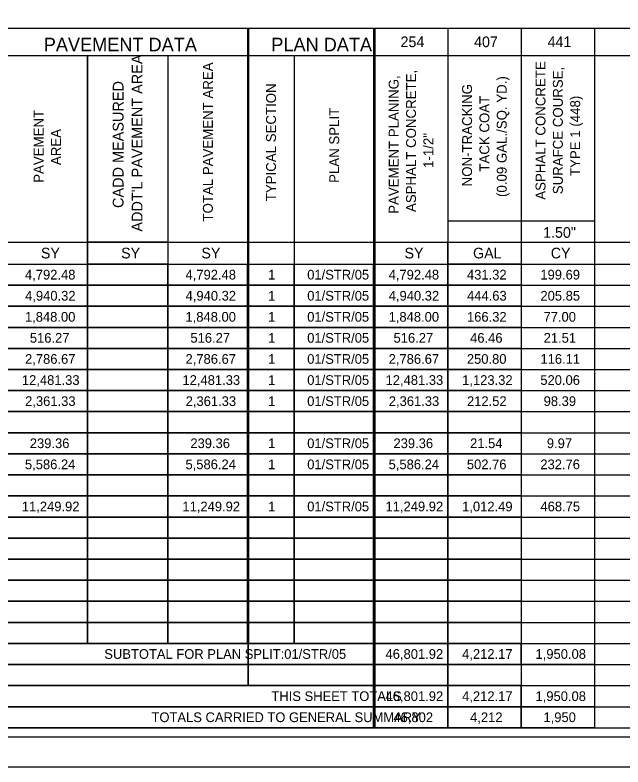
# Model space of a CAD drawing. Extents: x 0 to 34, y 0 to 22.
# Drawn here: x 9.99 to 20.23, y 0 to 12.66 of the extents above; entities that cross this region are included whole.
import ezdxf

# ---------------------------------------------------------------- set-up
doc = ezdxf.new("R2010")
doc.units = 0
for name, color, linetype in [('Default', 7, 'Continuous'), ('SH_Border', 7, 'Continuous'), ('SH_Cut_Line', 7, 'Continuous')]:
    doc.layers.add(name, color=color, linetype=linetype)

msp = doc.modelspace()

# ---------------------------------------------------------------- linework, layer by layer
at = {"layer": 'Default'}
for p, q in [((9.073, 12.437), (13.925, 12.437)), ((13.903, 12.437), (16.052, 12.437)), ((13.903, 12.437), (13.903, 2.079)), ((13.925, 12.437), (13.925, 2.079)), ((16.03, 12.437), (32, 12.437)), ((16.03, 12.437), (16.03, 0.66)), ((16.052, 12.437), (16.052, 0.66)), ((17.278, 12.437), (17.278, 0.66)), ((18.514, 12.437), (18.514, 0.66)), ((19.751, 12.437), (19.751, 0.66)), ((9.095, 11.976), (13.903, 11.976)), ((11.211, 11.976), (11.211, 2.079)), ((12.562, 11.976), (12.562, 2.079)), ((13.925, 11.976), (16.03, 11.976)), ((14.689, 11.976), (14.689, 2.079)), ((16.052, 11.976), (32, 11.976)), ((17.278, 9.191), (19.751, 9.191)), ((9.095, 8.836), (13.903, 8.836)), ((13.925, 8.836), (16.03, 8.836)), ((16.052, 8.836), (25.933, 8.836)), ((9.095, 8.464), (13.903, 8.464)), ((13.925, 8.464), (16.03, 8.464)), ((16.052, 8.464), (32, 8.464)), ((9.095, 8.109), (13.903, 8.109)), ((13.925, 8.109), (16.03, 8.109)), ((16.052, 8.109), (32, 8.109)), ((9.095, 7.754), (13.903, 7.754)), ((13.925, 7.754), (16.03, 7.754)), ((16.052, 7.754), (32, 7.754)), ((9.095, 7.4), (13.903, 7.4)), ((13.925, 7.4), (16.03, 7.4)), ((16.052, 7.4), (32, 7.4)), ((9.095, 7.045), (13.903, 7.045)), ((13.925, 7.045), (16.03, 7.045)), ((16.052, 7.045), (32, 7.045)), ((9.095, 6.69), (13.903, 6.69)), ((13.925, 6.69), (16.03, 6.69)), ((16.052, 6.69), (32, 6.69)), ((9.095, 6.335), (13.903, 6.335)), ((13.925, 6.335), (16.03, 6.335)), ((16.052, 6.335), (32, 6.335)), ((9.095, 5.981), (13.903, 5.981)), ((13.925, 5.981), (16.03, 5.981)), ((16.052, 5.981), (32, 5.981)), ((9.095, 5.626), (13.903, 5.626)), ((13.925, 5.626), (16.03, 5.626)), ((16.052, 5.626), (32, 5.626)), ((9.095, 5.271), (13.903, 5.271)), ((13.925, 5.271), (16.03, 5.271)), ((16.052, 5.271), (32, 5.271)), ((9.095, 4.916), (13.903, 4.916)), ((13.925, 4.916), (16.03, 4.916)), ((16.052, 4.916), (32, 4.916)), ((9.095, 4.562), (13.903, 4.562)), ((13.925, 4.562), (16.03, 4.562)), ((16.052, 4.562), (32, 4.562)), ((9.095, 4.207), (13.903, 4.207)), ((13.925, 4.207), (16.03, 4.207)), ((16.052, 4.207), (32, 4.207)), ((9.095, 3.852), (13.903, 3.852)), ((13.925, 3.852), (16.03, 3.852)), ((16.052, 3.852), (32, 3.852)), ((9.095, 3.498), (13.903, 3.498)), ((13.925, 3.498), (16.03, 3.498)), ((16.052, 3.498), (32, 3.498)), ((9.095, 3.143), (13.903, 3.143)), ((13.925, 3.143), (16.03, 3.143)), ((16.052, 3.143), (32, 3.143)), ((9.095, 2.788), (13.903, 2.788)), ((13.925, 2.788), (16.03, 2.788)), ((16.052, 2.788), (32, 2.788)), ((9.095, 2.433), (13.903, 2.433)), ((13.925, 2.433), (16.03, 2.433)), ((16.052, 2.433), (32, 2.433)), ((9.073, 2.079), (16.03, 2.079)), ((13.914, 2.079), (13.914, 1.369)), ((16.052, 2.079), (32, 2.079)), ((1.5, 1.724), (16.03, 1.724)), ((16.052, 1.724), (32, 1.724)), ((1.5, 1.369), (16.03, 1.369)), ((16.052, 1.369), (32, 1.369)), ((1.5, 1.014), (16.03, 1.014)), ((16.052, 1.014), (32, 1.014)), ((1.5, 0.66), (16.052, 0.66)), ((16.03, 0.66), (32, 0.66))]:
    msp.add_line(p, q, dxfattribs=at)
for points in [[(11.211, 11.976), (12.562, 11.976), (12.562, 8.836), (11.211, 8.836)], [(11.211, 8.836), (12.562, 8.836), (12.562, 8.464), (11.211, 8.464)], [(17.278, 8.836), (18.514, 8.836), (18.514, 8.464), (17.278, 8.464)], [(9.859, 8.464), (11.211, 8.464), (11.211, 8.109), (9.859, 8.109)], [(11.211, 8.464), (12.562, 8.464), (12.562, 8.109), (11.211, 8.109)], [(12.562, 8.464), (13.925, 8.464), (13.925, 8.109), (12.562, 8.109)], [(13.903, 8.464), (14.689, 8.464), (14.689, 8.109), (13.903, 8.109)], [(14.689, 8.464), (16.052, 8.464), (16.052, 8.109), (14.689, 8.109)], [(16.03, 8.464), (17.278, 8.464), (17.278, 8.109), (16.03, 8.109)], [(17.278, 8.464), (18.514, 8.464), (18.514, 8.109), (17.278, 8.109)], [(9.859, 8.109), (11.211, 8.109), (11.211, 7.754), (9.859, 7.754)], [(11.211, 8.109), (12.562, 8.109), (12.562, 7.754), (11.211, 7.754)], [(12.562, 8.109), (13.925, 8.109), (13.925, 7.754), (12.562, 7.754)], [(13.903, 8.109), (14.689, 8.109), (14.689, 7.754), (13.903, 7.754)], [(14.689, 8.109), (16.052, 8.109), (16.052, 7.754), (14.689, 7.754)], [(16.03, 8.109), (17.278, 8.109), (17.278, 7.754), (16.03, 7.754)], [(17.278, 8.109), (18.514, 8.109), (18.514, 7.754), (17.278, 7.754)], [(9.859, 7.754), (11.211, 7.754), (11.211, 7.4), (9.859, 7.4)], [(11.211, 7.754), (12.562, 7.754), (12.562, 7.4), (11.211, 7.4)], [(12.562, 7.754), (13.925, 7.754), (13.925, 7.4), (12.562, 7.4)], [(13.903, 7.754), (14.689, 7.754), (14.689, 7.4), (13.903, 7.4)], [(14.689, 7.754), (16.052, 7.754), (16.052, 7.4), (14.689, 7.4)], [(16.03, 7.754), (17.278, 7.754), (17.278, 7.4), (16.03, 7.4)], [(17.278, 7.754), (18.514, 7.754), (18.514, 7.4), (17.278, 7.4)], [(9.859, 7.4), (11.211, 7.4), (11.211, 7.045), (9.859, 7.045)], [(11.211, 7.4), (12.562, 7.4), (12.562, 7.045), (11.211, 7.045)], [(12.562, 7.4), (13.925, 7.4), (13.925, 7.045), (12.562, 7.045)], [(13.903, 7.4), (14.689, 7.4), (14.689, 7.045), (13.903, 7.045)], [(14.689, 7.4), (16.052, 7.4), (16.052, 7.045), (14.689, 7.045)], [(16.03, 7.4), (17.278, 7.4), (17.278, 7.045), (16.03, 7.045)], [(17.278, 7.4), (18.514, 7.4), (18.514, 7.045), (17.278, 7.045)], [(9.859, 7.045), (11.211, 7.045), (11.211, 6.69), (9.859, 6.69)], [(11.211, 7.045), (12.562, 7.045), (12.562, 6.69), (11.211, 6.69)], [(12.562, 7.045), (13.925, 7.045), (13.925, 6.69), (12.562, 6.69)], [(13.903, 7.045), (14.689, 7.045), (14.689, 6.69), (13.903, 6.69)], [(14.689, 7.045), (16.052, 7.045), (16.052, 6.69), (14.689, 6.69)], [(16.03, 7.045), (17.278, 7.045), (17.278, 6.69), (16.03, 6.69)], [(17.278, 7.045), (18.514, 7.045), (18.514, 6.69), (17.278, 6.69)], [(9.859, 6.69), (11.211, 6.69), (11.211, 6.335), (9.859, 6.335)], [(11.211, 6.69), (12.562, 6.69), (12.562, 6.335), (11.211, 6.335)], [(12.562, 6.69), (13.925, 6.69), (13.925, 6.335), (12.562, 6.335)], [(13.903, 6.69), (14.689, 6.69), (14.689, 6.335), (13.903, 6.335)], [(14.689, 6.69), (16.052, 6.69), (16.052, 6.335), (14.689, 6.335)], [(16.03, 6.69), (17.278, 6.69), (17.278, 6.335), (16.03, 6.335)], [(17.278, 6.69), (18.514, 6.69), (18.514, 6.335), (17.278, 6.335)], [(9.859, 6.335), (11.211, 6.335), (11.211, 5.981), (9.859, 5.981)], [(11.211, 6.335), (12.562, 6.335), (12.562, 5.981), (11.211, 5.981)], [(12.562, 6.335), (13.925, 6.335), (13.925, 5.981), (12.562, 5.981)], [(13.903, 6.335), (14.689, 6.335), (14.689, 5.981), (13.903, 5.981)], [(14.689, 6.335), (16.052, 6.335), (16.052, 5.981), (14.689, 5.981)], [(16.03, 6.335), (17.278, 6.335), (17.278, 5.981), (16.03, 5.981)], [(17.278, 6.335), (18.514, 6.335), (18.514, 5.981), (17.278, 5.981)], [(9.859, 5.981), (11.211, 5.981), (11.211, 5.626), (9.859, 5.626)], [(11.211, 5.981), (12.562, 5.981), (12.562, 5.626), (11.211, 5.626)], [(12.562, 5.981), (13.925, 5.981), (13.925, 5.626), (12.562, 5.626)], [(13.903, 5.981), (14.689, 5.981), (14.689, 5.626), (13.903, 5.626)], [(14.689, 5.981), (16.052, 5.981), (16.052, 5.626), (14.689, 5.626)], [(16.03, 5.981), (17.278, 5.981), (17.278, 5.626), (16.03, 5.626)], [(17.278, 5.981), (18.514, 5.981), (18.514, 5.626), (17.278, 5.626)], [(9.859, 5.626), (11.211, 5.626), (11.211, 5.271), (9.859, 5.271)], [(11.211, 5.626), (12.562, 5.626), (12.562, 5.271), (11.211, 5.271)], [(12.562, 5.626), (13.925, 5.626), (13.925, 5.271), (12.562, 5.271)], [(13.903, 5.626), (14.689, 5.626), (14.689, 5.271), (13.903, 5.271)], [(14.689, 5.626), (16.052, 5.626), (16.052, 5.271), (14.689, 5.271)], [(16.03, 5.626), (17.278, 5.626), (17.278, 5.271), (16.03, 5.271)], [(17.278, 5.626), (18.514, 5.626), (18.514, 5.271), (17.278, 5.271)], [(9.859, 5.271), (11.211, 5.271), (11.211, 4.916), (9.859, 4.916)], [(11.211, 5.271), (12.562, 5.271), (12.562, 4.916), (11.211, 4.916)], [(12.562, 5.271), (13.925, 5.271), (13.925, 4.916), (12.562, 4.916)], [(13.903, 5.271), (14.689, 5.271), (14.689, 4.916), (13.903, 4.916)], [(14.689, 5.271), (16.052, 5.271), (16.052, 4.916), (14.689, 4.916)], [(16.03, 5.271), (17.278, 5.271), (17.278, 4.916), (16.03, 4.916)], [(17.278, 5.271), (18.514, 5.271), (18.514, 4.916), (17.278, 4.916)], [(9.859, 4.916), (11.211, 4.916), (11.211, 4.562), (9.859, 4.562)], [(11.211, 4.916), (12.562, 4.916), (12.562, 4.562), (11.211, 4.562)], [(12.562, 4.916), (13.925, 4.916), (13.925, 4.562), (12.562, 4.562)], [(13.903, 4.916), (14.689, 4.916), (14.689, 4.562), (13.903, 4.562)], [(14.689, 4.916), (16.052, 4.916), (16.052, 4.562), (14.689, 4.562)], [(16.03, 4.916), (17.278, 4.916), (17.278, 4.562), (16.03, 4.562)], [(17.278, 4.916), (18.514, 4.916), (18.514, 4.562), (17.278, 4.562)], [(9.859, 4.562), (11.211, 4.562), (11.211, 4.207), (9.859, 4.207)], [(11.211, 4.562), (12.562, 4.562), (12.562, 4.207), (11.211, 4.207)], [(12.562, 4.562), (13.925, 4.562), (13.925, 4.207), (12.562, 4.207)], [(13.903, 4.562), (14.689, 4.562), (14.689, 4.207), (13.903, 4.207)], [(14.689, 4.562), (16.052, 4.562), (16.052, 4.207), (14.689, 4.207)], [(16.03, 4.562), (17.278, 4.562), (17.278, 4.207), (16.03, 4.207)], [(17.278, 4.562), (18.514, 4.562), (18.514, 4.207), (17.278, 4.207)], [(9.859, 4.207), (11.211, 4.207), (11.211, 3.852), (9.859, 3.852)], [(11.211, 4.207), (12.562, 4.207), (12.562, 3.852), (11.211, 3.852)], [(12.562, 4.207), (13.925, 4.207), (13.925, 3.852), (12.562, 3.852)], [(13.903, 4.207), (14.689, 4.207), (14.689, 3.852), (13.903, 3.852)], [(14.689, 4.207), (16.052, 4.207), (16.052, 3.852), (14.689, 3.852)], [(16.03, 4.207), (17.278, 4.207), (17.278, 3.852), (16.03, 3.852)], [(17.278, 4.207), (18.514, 4.207), (18.514, 3.852), (17.278, 3.852)], [(9.859, 3.852), (11.211, 3.852), (11.211, 3.498), (9.859, 3.498)], [(11.211, 3.852), (12.562, 3.852), (12.562, 3.498), (11.211, 3.498)], [(12.562, 3.852), (13.925, 3.852), (13.925, 3.498), (12.562, 3.498)], [(13.903, 3.852), (14.689, 3.852), (14.689, 3.498), (13.903, 3.498)], [(14.689, 3.852), (16.052, 3.852), (16.052, 3.498), (14.689, 3.498)], [(16.03, 3.852), (17.278, 3.852), (17.278, 3.498), (16.03, 3.498)], [(17.278, 3.852), (18.514, 3.852), (18.514, 3.498), (17.278, 3.498)], [(9.859, 3.498), (11.211, 3.498), (11.211, 3.143), (9.859, 3.143)], [(11.211, 3.498), (12.562, 3.498), (12.562, 3.143), (11.211, 3.143)], [(12.562, 3.498), (13.925, 3.498), (13.925, 3.143), (12.562, 3.143)], [(13.903, 3.498), (14.689, 3.498), (14.689, 3.143), (13.903, 3.143)], [(14.689, 3.498), (16.052, 3.498), (16.052, 3.143), (14.689, 3.143)], [(16.03, 3.498), (17.278, 3.498), (17.278, 3.143), (16.03, 3.143)], [(17.278, 3.498), (18.514, 3.498), (18.514, 3.143), (17.278, 3.143)], [(9.859, 3.143), (11.211, 3.143), (11.211, 2.788), (9.859, 2.788)], [(11.211, 3.143), (12.562, 3.143), (12.562, 2.788), (11.211, 2.788)], [(12.562, 3.143), (13.925, 3.143), (13.925, 2.788), (12.562, 2.788)], [(13.903, 3.143), (14.689, 3.143), (14.689, 2.788), (13.903, 2.788)], [(14.689, 3.143), (16.052, 3.143), (16.052, 2.788), (14.689, 2.788)], [(16.03, 3.143), (17.278, 3.143), (17.278, 2.788), (16.03, 2.788)], [(17.278, 3.143), (18.514, 3.143), (18.514, 2.788), (17.278, 2.788)], [(9.859, 2.788), (11.211, 2.788), (11.211, 2.433), (9.859, 2.433)], [(11.211, 2.788), (12.562, 2.788), (12.562, 2.433), (11.211, 2.433)], [(12.562, 2.788), (13.925, 2.788), (13.925, 2.433), (12.562, 2.433)], [(13.903, 2.788), (14.689, 2.788), (14.689, 2.433), (13.903, 2.433)], [(14.689, 2.788), (16.052, 2.788), (16.052, 2.433), (14.689, 2.433)], [(16.03, 2.788), (17.278, 2.788), (17.278, 2.433), (16.03, 2.433)], [(17.278, 2.788), (18.514, 2.788), (18.514, 2.433), (17.278, 2.433)], [(9.859, 2.433), (11.211, 2.433), (11.211, 2.079), (9.859, 2.079)], [(11.211, 2.433), (12.562, 2.433), (12.562, 2.079), (11.211, 2.079)], [(12.562, 2.433), (13.925, 2.433), (13.925, 2.079), (12.562, 2.079)], [(13.903, 2.433), (14.689, 2.433), (14.689, 2.079), (13.903, 2.079)], [(14.689, 2.433), (16.052, 2.433), (16.052, 2.079), (14.689, 2.079)], [(16.03, 2.433), (17.278, 2.433), (17.278, 2.079), (16.03, 2.079)], [(17.278, 2.433), (18.514, 2.433), (18.514, 2.079), (17.278, 2.079)], [(1.5, 2.079), (13.914, 2.079), (13.914, 1.724), (1.5, 1.724)], [(13.914, 2.079), (16.041, 2.079), (16.041, 1.724), (13.914, 1.724)], [(16.03, 2.079), (17.278, 2.079), (17.278, 1.724), (16.03, 1.724)], [(17.278, 2.079), (18.514, 2.079), (18.514, 1.724), (17.278, 1.724)], [(18.514, 2.079), (19.751, 2.079), (19.751, 1.724), (18.514, 1.724)], [(1.5, 1.724), (13.914, 1.724), (13.914, 1.369), (1.5, 1.369)], [(13.914, 1.724), (16.041, 1.724), (16.041, 1.369), (13.914, 1.369)], [(16.03, 1.724), (17.278, 1.724), (17.278, 1.369), (16.03, 1.369)], [(17.278, 1.724), (18.514, 1.724), (18.514, 1.369), (17.278, 1.369)], [(1.5, 1.369), (16.041, 1.369), (16.041, 1.014), (1.5, 1.014)], [(16.03, 1.369), (17.278, 1.369), (17.278, 1.014), (16.03, 1.014)], [(17.278, 1.369), (18.514, 1.369), (18.514, 1.014), (17.278, 1.014)], [(18.514, 1.369), (19.751, 1.369), (19.751, 1.014), (18.514, 1.014)], [(1.5, 1.014), (16.041, 1.014), (16.041, 0.66), (1.5, 0.66)], [(16.03, 1.014), (17.278, 1.014), (17.278, 0.66), (16.03, 0.66)], [(17.278, 1.014), (18.514, 1.014), (18.514, 0.66), (17.278, 0.66)], [(18.514, 1.014), (19.751, 1.014), (19.751, 0.66), (18.514, 0.66)]]:
    msp.add_lwpolyline(points, close=True, dxfattribs=at)
at = {"layer": 'SH_Border'}
msp.add_lwpolyline([(1.5, 21.5), (33.5, 21.5), (33.5, 0.5), (1.5, 0.5)], close=True, dxfattribs=at)
at = {"layer": 'SH_Cut_Line'}
msp.add_lwpolyline([(0, 0), (34, 0), (34, 22), (0, 22)], close=True, dxfattribs=at)

# ---------------------------------------------------------------- texts
at = {"layer": 'Default'}
for s, height, p in [('254', 0.1795, (16.483, 12.116)), ('407', 0.1795, (17.721, 12.116)), ('441', 0.1795, (18.959, 12.116)), ('PAVEMENT DATA', 0.22845, (10.474, 12.046)), ('PLAN DATA', 0.2284, (14.306, 12.046)), ('1.50"', 0.1795, (18.884, 8.907)), ('SY', 0.1795, (10.426, 8.56)), ('SY', 0.1795, (11.777, 8.56)), ('SY', 0.1795, (13.129, 8.56)), ('SY', 0.1795, (16.55, 8.56)), ('GAL', 0.1795, (17.704, 8.56)), ('CY', 0.1795, (19.013, 8.56)), ('4,792.48', 0.1632, (10.158, 8.205)), ('4,792.48', 0.1632, (12.862, 8.205)), ('1', 0.163, (14.253, 8.205)), ('01/STR/05', 0.1632, (14.911, 8.205)), ('4,792.48', 0.1632, (16.283, 8.205)), ('431.32', 0.1632, (17.602, 8.205)), ('199.69', 0.1632, (18.838, 8.205)), ('4,940.32', 0.1632, (10.16, 7.85)), ('4,940.32', 0.1632, (12.863, 7.85)), ('1', 0.163, (14.253, 7.85)), ('01/STR/05', 0.1632, (14.911, 7.85)), ('4,940.32', 0.1632, (16.284, 7.85)), ('444.63', 0.1632, (17.603, 7.85)), ('205.85', 0.1632, (18.839, 7.85)), ('1,848.00', 0.1632, (10.157, 7.495)), ('1,848.00', 0.1632, (12.861, 7.495)), ('1', 0.163, (14.253, 7.495)), ('01/STR/05', 0.1632, (14.911, 7.495)), ('1,848.00', 0.1632, (16.282, 7.495)), ('166.32', 0.1632, (17.602, 7.495)), ('77.00', 0.1632, (18.891, 7.495)), ('516.27', 0.1632, (10.24, 7.141)), ('516.27', 0.1632, (12.944, 7.141)), ('1', 0.163, (14.253, 7.141)), ('01/STR/05', 0.1632, (14.911, 7.141)), ('516.27', 0.1632, (16.365, 7.141)), ('46.46', 0.1632, (17.655, 7.141)), ('21.51', 0.1632, (18.893, 7.141)), ('2,786.67', 0.1632, (10.159, 6.786)), ('2,786.67', 0.1632, (12.862, 6.786)), ('1', 0.163, (14.253, 6.786)), ('01/STR/05', 0.1632, (14.911, 6.786)), ('2,786.67', 0.1632, (16.283, 6.786)), ('250.80', 0.1632, (17.6, 6.786)), ('116.11', 0.1632, (18.839, 6.786)), ('12,481.33', 0.1632, (10.106, 6.431)), ('12,481.33', 0.1632, (12.81, 6.431)), ('1', 0.163, (14.253, 6.431)), ('01/STR/05', 0.1632, (14.911, 6.431)), ('12,481.33', 0.1632, (16.231, 6.431)), ('1,123.32', 0.1632, (17.521, 6.431)), ('520.06', 0.1632, (18.837, 6.431)), ('2,361.33', 0.1632, (10.16, 6.076)), ('2,361.33', 0.1632, (12.864, 6.076)), ('1', 0.163, (14.253, 6.076)), ('01/STR/05', 0.1632, (14.911, 6.076)), ('2,361.33', 0.1632, (16.285, 6.076)), ('212.52', 0.1632, (17.602, 6.076)), ('98.39', 0.1632, (18.893, 6.076)), ('239.36', 0.1632, (10.239, 5.367)), ('239.36', 0.1632, (12.943, 5.367)), ('1', 0.163, (14.253, 5.367)), ('01/STR/05', 0.1632, (14.911, 5.367)), ('239.36', 0.1632, (16.364, 5.367)), ('21.54', 0.1632, (17.654, 5.367)), ('9.97', 0.1632, (18.947, 5.367)), ('5,586.24', 0.1632, (10.157, 5.012)), ('5,586.24', 0.1632, (12.861, 5.012)), ('1', 0.163, (14.253, 5.012)), ('01/STR/05', 0.1632, (14.911, 5.012)), ('5,586.24', 0.1632, (16.282, 5.012)), ('502.76', 0.1632, (17.6, 5.012)), ('232.76', 0.1632, (18.837, 5.012)), ('11,249.92', 0.1632, (10.105, 4.303)), ('11,249.92', 0.1632, (12.809, 4.303)), ('1', 0.163, (14.253, 4.303)), ('01/STR/05', 0.1632, (14.911, 4.303)), ('11,249.92', 0.1632, (16.23, 4.303)), ('1,012.49', 0.1632, (17.52, 4.303)), ('468.75', 0.1632, (18.839, 4.303)), ('SUBTOTAL FOR PLAN SPLIT:', 0.16318, (11.494, 1.82)), ('01/STR/05', 0.1632, (14.524, 1.82)), ('46,801.92', 0.1632, (16.23, 1.82)), ('4,212.17', 0.1632, (17.52, 1.82)), ('1,950.08', 0.1632, (18.756, 1.82)), ('THIS SHEET TOTALS', 0.16318, (14.309, 1.11)), ('46,801.92', 0.1632, (16.23, 1.11)), ('4,212.17', 0.1632, (17.52, 1.11)), ('1,950.08', 0.1632, (18.756, 1.11)), ('TOTALS CARRIED TO GENERAL SUMMARY', 0.16318, (12.289, 0.755)), ('46,802', 0.1632, (16.363, 0.755)), ('4,212', 0.1632, (17.654, 0.755)), ('1,950', 0.1632, (18.89, 0.755))]:
    msp.add_text(s, height=height, dxfattribs=at).set_placement(p)
for s, height, p in [("ADDT'L PAVEMENT AREA", 0.18201, (12.137, 9.011)), ('TOTAL PAVEMENT AREA', 0.16684, (13.322, 9.181)), ('ASPHALT CONCRETE ', 0.16684, (18.924, 9.548)), ('ASPHALT CONCRETE, ', 0.16684, (16.743, 9.341)), ('SURAFCE COURSE, ', 0.16684, (19.216, 9.641)), ('CADD MEASURED', 0.18201, (11.818, 9.409)), ('PAVEMENT PLANING, ', 0.16684, (16.451, 9.311)), ('(0.09 GAL./SQ. YD.)', 0.16684, (18.271, 9.594)), ('TYPICAL SECTION', 0.16684, (14.385, 9.523)), ('NON-TRACKING ', 0.16684, (17.687, 9.773)), ('TACK COAT', 0.1668, (17.979, 10.021)), ('TYPE 1 (448)', 0.16684, (19.508, 9.947)), ('PAVEMENT', 0.1668, (10.472, 9.833)), ('PLAN SPLIT', 0.1668, (15.449, 9.831)), ('AREA', 0.1668, (10.764, 10.131)), ('1-1/2"', 0.1668, (17.035, 10.083))]:
    msp.add_text(s, height=height, rotation=90, dxfattribs=at).set_placement(p)

doc.saveas('drawing.dxf')
